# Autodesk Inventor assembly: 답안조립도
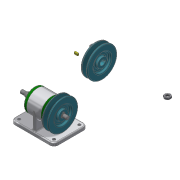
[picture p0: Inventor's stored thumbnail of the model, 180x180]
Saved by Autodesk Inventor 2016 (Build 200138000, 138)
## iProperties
Created: 2019-09
Part Number: 답안조립도
Material: 일반
Document SubType Name: Assembly
Designer: Administrator
Author: Administrator
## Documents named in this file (10)
- C:\Users\Administrator\Desktop\490904v1046\답안조립도.iam
- C:\Users\Administrator\Desktop\490904v1046\본체.ipt
- C:\Users\Administrator\Desktop\490904v1046\베어링 6004.ipt
- C:\Users\Administrator\Desktop\490904v1046\축.ipt
- C:\Users\Administrator\Desktop\490904v1046\오일 실 17 30 5.ipt
- C:\Users\Administrator\Desktop\490904v1046\커버.ipt
- C:\Users\Administrator\Desktop\490904v1046\볼트 M4.ipt
- C:\Users\Administrator\Desktop\490904v1046\V-벨트풀리.ipt
- C:\Users\Administrator\Desktop\490904v1046\너트 M10x1.ipt
- C:\Users\Administrator\Desktop\490904v1046\키 5 x 5 x 12.ipt
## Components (2 placed, 1 different names)
1. V-벨트풀리:1
2. V-벨트풀리:2 — 각도:1
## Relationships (1: Angle 1)
- 각도:1 [Angle]: V-벨트풀리:2
